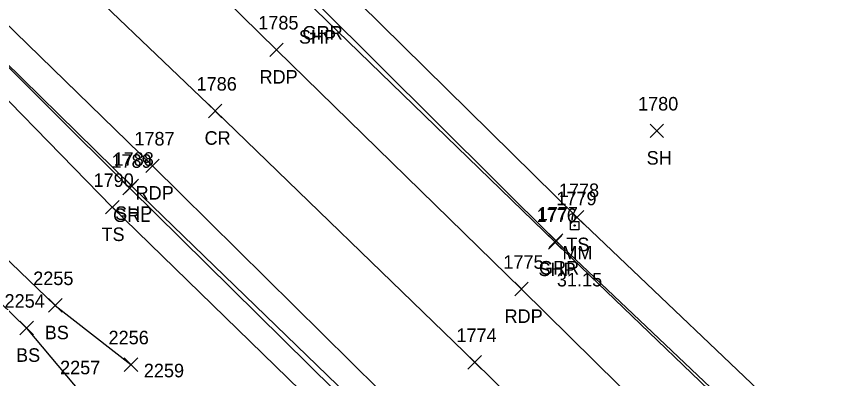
# Model space of a CAD drawing. Extents: x 1647574 to 1652703, y 212895 to 228670.
# Drawn here: x 1648547.8 to 1648670.8, y 227561.3 to 227614.7 of the extents above; entities that cross this region are included whole.
import ezdxf

# ---------------------------------------------------------------- set-up
doc = ezdxf.new("R2010")
doc.units = 0
for name, color, linetype in [('L_A', 7, 'Continuous'), ('L_I', 7, 'Continuous'), ('L_TIC', 7, 'Continuous'), ('LELB', 7, 'Continuous'), ('P_A', 7, 'Continuous'), ('P_I', 7, 'Continuous'), ('P_TIC', 7, 'Continuous'), ('PET', 7, 'Continuous'), ('PRC', 7, 'Continuous'), ('PSP', 7, 'Continuous'), ('R_A', 7, 'Continuous'), ('R_I', 7, 'Continuous'), ('R_TIC', 7, 'Continuous'), ('RGR', 7, 'Continuous'), ('S_A', 7, 'Continuous'), ('S_C', 7, 'Continuous'), ('S_I', 7, 'Continuous'), ('SRM', 7, 'Continuous')]:
    doc.layers.add(name, color=color, linetype=linetype)

msp = doc.modelspace()

# ---------------------------------------------------------------- linework, layer by layer
at = {"layer": 'L_TIC'}
for points in [[(1648641.52, 227596.88), (1648643.52, 227598.88)], [(1648643.52, 227596.88), (1648641.52, 227598.88)], [(1648560.98, 227585.59), (1648562.98, 227587.59)], [(1648562.98, 227585.59), (1648560.98, 227587.59)], [(1648629.72, 227584.09), (1648631.72, 227586.09)], [(1648631.72, 227584.09), (1648629.72, 227586.09)], [(1648552.55, 227571.08), (1648554.55, 227573.08)], [(1648554.55, 227571.08), (1648552.55, 227573.08)], [(1648548.31, 227567.74), (1648550.31, 227569.74)], [(1648550.31, 227567.74), (1648548.31, 227569.74)], [(1648563.74, 227562.33), (1648565.74, 227564.33)], [(1648565.74, 227562.33), (1648563.74, 227564.33)], [(1648563.74, 227562.33), (1648565.74, 227564.33)], [(1648565.74, 227562.33), (1648563.74, 227564.33)]]:
    msp.add_lwpolyline(points, dxfattribs=at)
at = {"layer": 'LELB'}
for points in [[(1648005.17, 228084.65), (1648023.65, 228068.5), (1648050.66, 228049.08), (1648084, 228027.44), (1648113.5, 228007.83), (1648147.29, 227982.73), (1648182.2, 227955.34), (1648213, 227923.38), (1648241.53, 227889), (1648267.07, 227861.14), (1648299.05, 227827.09), (1648330.77, 227794.94), (1648361.15, 227762.57), (1648392.5, 227731.8), (1648431.64, 227692.37), (1648464.56, 227657.5), (1648493.11, 227630.36), (1648521, 227603.29), (1648553.55, 227572.08), (1648564.74, 227563.33)], [(1648003.1, 228082.75), (1648021.4, 228065.95), (1648044.73, 228045.59), (1648079.17, 228018.19), (1648101.81, 227996.84), (1648138.98, 227971.46), (1648165.99, 227945.56), (1648168.81, 227943.47), (1648170.35, 227941.98), (1648172.46, 227939.54), (1648204.47, 227916.76), (1648236.47, 227884.75), (1648262.27, 227857.29), (1648293.8, 227821.06), (1648324.53, 227790.88), (1648359.53, 227760.77), (1648386.88, 227728.2), (1648427.75, 227689.04), (1648461.36, 227653.83), (1648490.92, 227628.14), (1648517.86, 227599.3), (1648549.31, 227568.74), (1648557.52, 227558.9)], [(1648859.74, 227356.65), (1648840.12, 227378.91), (1648802.29, 227415.99), (1648770.94, 227445.62), (1648740.28, 227477.01), (1648708.8, 227506.87), (1648686.01, 227530.68), (1648664.68, 227552.78), (1648630.72, 227585.09), (1648595.33, 227619.93), (1648569.85, 227644.46), (1648530.91, 227681.62), (1648503.48, 227711.09), (1648474.08, 227742.1), (1648442.94, 227774.58), (1648417.61, 227803.67), (1648387.3, 227839.86), (1648354.19, 227879.71), (1648321.73, 227919.78)], [(1648774.58, 227389.56), (1648743.29, 227416.76), (1648711.06, 227445.83), (1648678.9, 227476.26), (1648653.94, 227498.58), (1648629.18, 227520.51), (1648599.07, 227550.48), (1648561.98, 227586.59), (1648537.34, 227611.83), (1648495.7, 227652.57), (1648469.81, 227680.64), (1648438.58, 227713.56), (1648409.77, 227744.99), (1648382.96, 227775.49), (1648351.84, 227812.3), (1648319.03, 227851.85)]]:
    msp.add_lwpolyline(points, dxfattribs=at)
at = {"layer": 'P_TIC'}
for points in [[(1648585.27, 227608.85), (1648587.27, 227610.85)], [(1648587.27, 227608.85), (1648585.27, 227610.85)], [(1648576.2, 227599.82), (1648578.2, 227601.82)], [(1648578.2, 227599.82), (1648576.2, 227601.82)], [(1648566.94, 227591.71), (1648568.94, 227593.71)], [(1648568.94, 227591.71), (1648566.94, 227593.71)], [(1648563.87, 227588.71), (1648565.87, 227590.71)], [(1648565.87, 227588.71), (1648563.87, 227590.71)], [(1648626.48, 227580.41), (1648628.48, 227582.41)], [(1648628.48, 227580.41), (1648626.48, 227582.41)], [(1648621.51, 227573.49), (1648623.51, 227575.49)], [(1648623.51, 227573.49), (1648621.51, 227575.49)], [(1648614.58, 227562.67), (1648616.58, 227564.67)], [(1648616.58, 227562.67), (1648614.58, 227564.67)]]:
    msp.add_lwpolyline(points, dxfattribs=at)
at = {"layer": 'PET'}
for points in [[(1648859.77, 227350.01), (1648834.8, 227373.42), (1648794.62, 227411.18), (1648764.14, 227439.93), (1648732.84, 227469.15), (1648700.82, 227498.96), (1648676.82, 227521.55), (1648654.81, 227542.65), (1648622.51, 227574.49), (1648586.27, 227609.85), (1648560.73, 227634.92), (1648521.71, 227673.76), (1648494.06, 227702.04), (1648464.63, 227733.46), (1648434.45, 227766.66), (1648408.12, 227796.3), (1648377.39, 227832.24), (1648343.92, 227872.68), (1648312.18, 227912.42)], [(1648813.95, 227358.94), (1648778.04, 227392.69), (1648747.29, 227421.36), (1648716.15, 227450.61), (1648683.9, 227480.61), (1648659.12, 227504.21), (1648636.13, 227525.99), (1648605.63, 227555.48), (1648567.94, 227592.71), (1648543.86, 227616.05), (1648502.53, 227657.19), (1648475.06, 227685.79), (1648444.59, 227717.74), (1648415.43, 227749.69), (1648388.57, 227780.05), (1648357.18, 227817.31), (1648324.35, 227856.66)]]:
    msp.add_lwpolyline(points, dxfattribs=at)
at = {"layer": 'PRC'}
msp.add_lwpolyline([(1648838.07, 227353.54), (1648807.35, 227381.57), (1648786.43, 227402.05), (1648755.91, 227430.19), (1648724.74, 227459.82), (1648692.84, 227489.5), (1648667.2, 227513.57), (1648644.8, 227535.1), (1648615.58, 227563.67), (1648577.2, 227600.82), (1648552.11, 227624.84), (1648512.09, 227665.31), (1648484.94, 227693.32), (1648454.59, 227725.67), (1648425.77, 227757.32), (1648398.45, 227788.16), (1648367.06, 227824.4), (1648333.96, 227865.19)], dxfattribs=at)
at = {"layer": 'PSP'}
for points in [[(1648862.79, 227349.77), (1648858.81, 227353.71), (1648837.2, 227376.43), (1648798.17, 227413.97), (1648737.5, 227474.33), (1648707.27, 227504.55), (1648683.25, 227528.38), (1648680.78, 227530.89), (1648661.55, 227548.7), (1648627.48, 227581.41), (1648592.06, 227615.76), (1648566.89, 227641.29), (1648529.07, 227680.17), (1648501.07, 227708.87), (1648471.98, 227739.97), (1648441.35, 227773.22), (1648415.73, 227802.3), (1648385.43, 227838.08), (1648352.03, 227878.52), (1648319.68, 227918.25)], [(1648862.79, 227349.77), (1648859.77, 227350.01), (1648838.07, 227353.54), (1648813.95, 227358.94), (1648808.77, 227359.65), (1648801.07, 227367.02), (1648799.4, 227367.69), (1648775.51, 227390.23), (1648744.84, 227418.75), (1648714.06, 227447.93), (1648681.62, 227478.36), (1648656.94, 227501.72), (1648633.18, 227523.88), (1648602.92, 227552.91), (1648564.87, 227589.71), (1648540.52, 227613.53), (1648499.1, 227654.74), (1648471.89, 227682.44), (1648441.11, 227715.05), (1648412.29, 227746.76), (1648385.5, 227777.34), (1648354.02, 227814.19), (1648321.06, 227853.92)]]:
    msp.add_lwpolyline(points, dxfattribs=at)
at = {"layer": 'R_TIC'}
for points in [[(1648563.56, 227588.41), (1648565.56, 227590.41)], [(1648565.56, 227588.41), (1648563.56, 227590.41)], [(1648626.6, 227580.64), (1648628.6, 227582.64)], [(1648628.6, 227580.64), (1648626.6, 227582.64)]]:
    msp.add_lwpolyline(points, dxfattribs=at)
at = {"layer": 'RGR'}
for points in [[(1648799.4, 227367.69), (1648775.21, 227390.09), (1648744.67, 227418.58), (1648713.63, 227447.71), (1648681.41, 227478.1), (1648656.75, 227501.4), (1648632.98, 227523.33), (1648602.41, 227552.12), (1648564.56, 227589.41), (1648540.3, 227613.5), (1648498.82, 227654.38), (1648471.44, 227682.07), (1648440.86, 227714.66), (1648411.81, 227746.44), (1648384.97, 227776.71), (1648353.62, 227813.75), (1648320.77, 227853.11)], [(1648858.35, 227355.78), (1648837.72, 227376.91), (1648798.67, 227414.48), (1648769.05, 227444.38), (1648738.03, 227474.66), (1648707.59, 227505.32), (1648682.61, 227530.03), (1648661.9, 227549.13), (1648627.6, 227581.64), (1648592.63, 227616.36), (1648580.49, 227628.61)]]:
    msp.add_lwpolyline(points, dxfattribs=at)
at = {"layer": 'SRM'}
msp.add_lwpolyline([(1648629.73, 227584.5), (1648630.98, 227584.5), (1648630.98, 227583.25), (1648629.73, 227583.25)], close=True, dxfattribs=at)
msp.add_circle((1648630.36, 227583.88), 0.0833, dxfattribs=at)

# ---------------------------------------------------------------- texts
at = {"layer": 'L_A'}
for s, p in [('SH', (1648641.01, 227592.88)), ('TS', (1648560.39, 227581.59)), ('TS', (1648629.13, 227580.09)), ('BS', (1648551.99, 227567.08)), ('BS', (1648547.75, 227563.74))]:
    msp.add_text(s, height=2, dxfattribs=at).set_placement(p)
at = {"layer": 'L_I'}
for s, p in [('1780', (1648639.74, 227600.88)), ('1790', (1648559.21, 227589.59)), ('1778', (1648628.03, 227588.09)), ('2255', (1648550.29, 227575.08)), ('2254', (1648546.05, 227571.74)), ('2256', (1648561.43, 227566.33)), ('2256', (1648561.43, 227566.33)), ('2257', (1648554.26, 227561.9)), ('2257', (1648554.26, 227561.9)), ('2259', (1648566.65, 227561.45))]:
    msp.add_text(s, height=2, dxfattribs=at).set_placement(p)
at = {"layer": 'P_A'}
for s, p in [('SHP', (1648589.59, 227610.76)), ('RDP', (1648583.76, 227604.85)), ('CR', (1648575.63, 227595.82)), ('RDP', (1648565.43, 227587.71)), ('SHP', (1648562.4, 227584.71)), ('SHP', (1648625.02, 227576.41)), ('RDP', (1648620, 227569.49))]:
    msp.add_text(s, height=2, dxfattribs=at).set_placement(p)
at = {"layer": 'P_I'}
for s, p in [('1785', (1648583.57, 227612.85)), ('1786', (1648574.45, 227603.82)), ('1787', (1648565.25, 227595.71)), ('1788', (1648562.17, 227592.71)), ('1776', (1648624.74, 227584.41)), ('1775', (1648619.82, 227577.49)), ('1774', (1648612.88, 227566.67))]:
    msp.add_text(s, height=2, dxfattribs=at).set_placement(p)
at = {"layer": 'R_A'}
for s, p in [('GRR', (1648590.12, 227611.36)), ('GRL', (1648562.1, 227584.41)), ('GRR', (1648625.09, 227576.64))]:
    msp.add_text(s, height=2, dxfattribs=at).set_placement(p)
at = {"layer": 'R_I'}
for s, p in [('1789', (1648561.86, 227592.41)), ('1777', (1648624.91, 227584.64))]:
    msp.add_text(s, height=2, dxfattribs=at).set_placement(p)
at = {"layer": 'S_A'}
msp.add_text('MM', height=2, dxfattribs=at).set_placement((1648628.55, 227578.88))
at = {"layer": 'S_C'}
msp.add_text('31.15', height=2, dxfattribs=at).set_placement((1648627.74, 227574.88))
at = {"layer": 'S_I'}
msp.add_text('1779', height=2, dxfattribs=at).set_placement((1648627.66, 227586.88))

doc.saveas('drawing.dxf')
